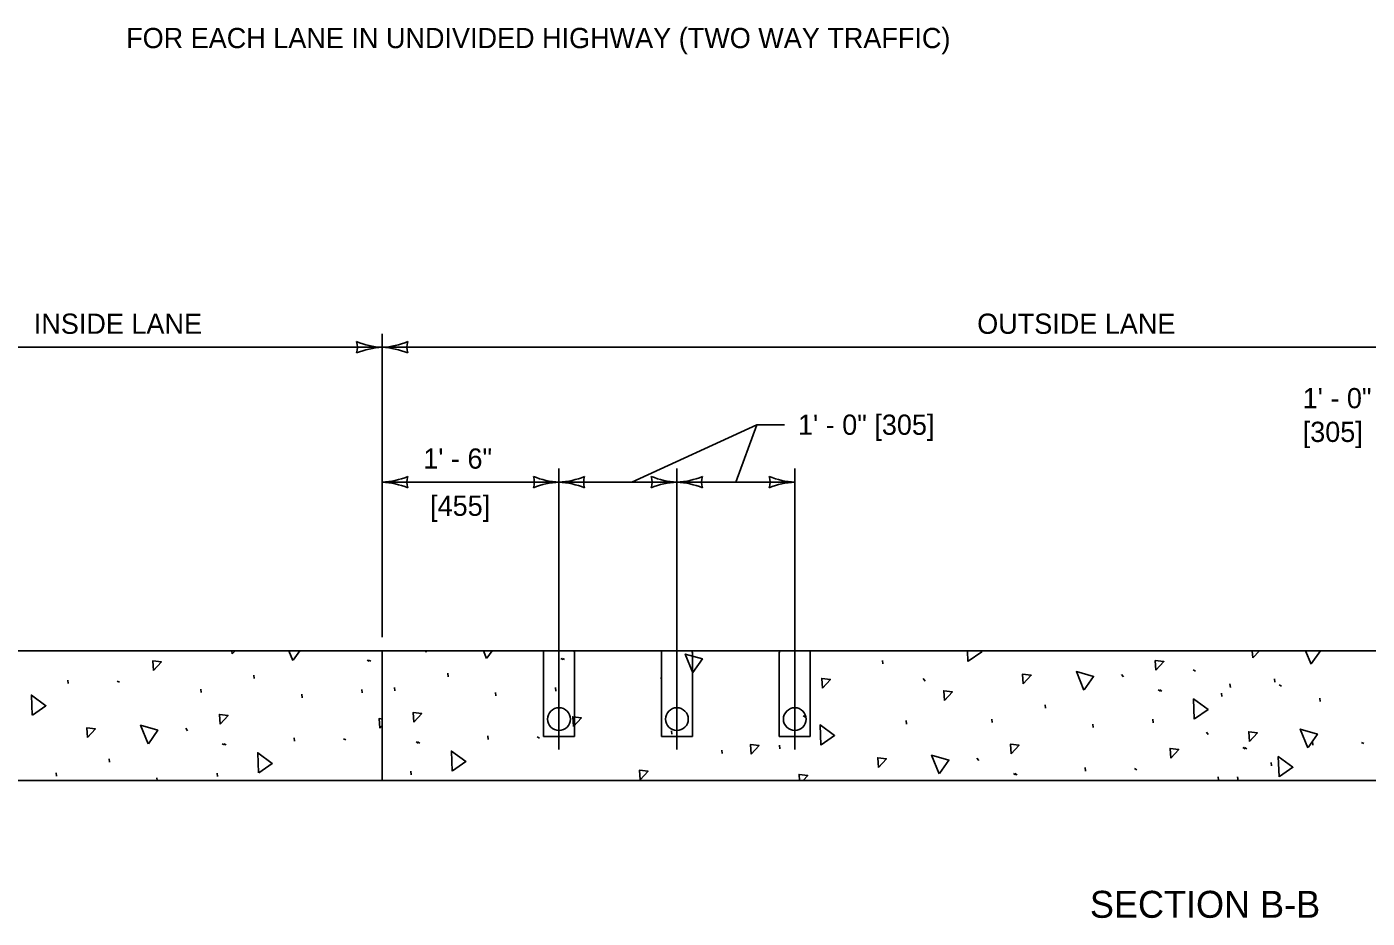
# Model space of a CAD drawing. Extents: x 49991.4 to 50021, y 49987.6 to 50011.4.
# Drawn here: x 50002.055 to 50006.035, y 49990.736 to 49993.381 of the extents above; entities that cross this region are included whole.
import ezdxf

# ---------------------------------------------------------------- set-up
doc = ezdxf.new("R2010")
doc.units = 0
for name, color, linetype in [('Level 1', 7, 'Continuous'), ('Level 2', 7, 'Continuous'), ('Level 3', 7, 'Continuous'), ('Level 4', 7, 'Continuous'), ('Level 5', 7, 'Continuous'), ('Level 9', 7, 'Continuous')]:
    doc.layers.add(name, color=color, linetype=linetype)

msp = doc.modelspace()

# ---------------------------------------------------------------- linework, layer by layer
at = {"layer": 'Level 1'}
for p, q in [((50001.6187, 49991.5298), (50007.3102, 49991.5298)), ((50003.1103, 49991.5298), (50003.1103, 49991.1448)), ((50001.6187, 49991.1448), (50003.1125, 49991.1448)), ((50003.1125, 49991.1448), (50007.3102, 49991.1448))]:
    msp.add_line(p, q, dxfattribs=at)
at = {"layer": 'Level 3'}
for p, q in [((50003.1103, 49991.5698), (50003.1103, 49992.4698)), ((50003.1103, 49992.4298), (50001.6187, 49992.4298)), ((50007.3102, 49992.4298), (50003.1103, 49992.4298)), ((50004.2228, 49992.2002), (50004.3048, 49992.2002)), ((50003.6353, 49992.0298), (50003.1103, 49992.0298)), ((50003.9853, 49992.0298), (50003.6353, 49992.0298)), ((50004.3353, 49992.0298), (50003.9853, 49992.0298))]:
    msp.add_line(p, q, dxfattribs=at)
msp.add_lwpolyline([(50003.8515, 49992.0298), (50004.2228, 49992.2002), (50004.1603, 49992.0298)], dxfattribs=at)
for centre in [(50003.6353, 49991.3267), (50003.9853, 49991.3267), (50004.3353, 49991.3267)]:
    msp.add_circle(centre, 0.0338, dxfattribs=at)
for centre, radius, start, end in [((50003.1194, 49992.6519), 0.2223, 247.456, 267.6395), ((50002.9821, 49992.4298), 0.0548, 342.1388, 17.8612), ((50003.1218, 49992.1971), 0.233, 92.8273, 112.0772), ((50003.1011, 49992.6519), 0.2223, 272.3605, 292.544), ((50003.0988, 49992.1971), 0.233, 67.9228, 87.1727), ((50003.2385, 49992.4298), 0.0548, 162.1388, 197.8612), ((50003.1011, 49992.2519), 0.2223, 272.3605, 292.544), ((50003.0988, 49991.7971), 0.233, 67.9228, 87.1727), ((50003.2385, 49992.0298), 0.0548, 162.1388, 197.8612), ((50003.5071, 49992.0298), 0.0548, 342.1388, 17.8612), ((50003.6468, 49992.2625), 0.233, 247.9228, 267.1727), ((50003.6444, 49991.8076), 0.2223, 92.3605, 112.544), ((50003.6261, 49992.2519), 0.2223, 272.3605, 292.544), ((50003.6238, 49991.7971), 0.233, 67.9228, 87.1727), ((50003.7635, 49992.0298), 0.0548, 162.1388, 197.8612), ((50003.8571, 49992.0298), 0.0548, 342.1388, 17.8612), ((50003.9968, 49992.2625), 0.233, 247.9228, 267.1727), ((50003.9944, 49991.8076), 0.2223, 92.3605, 112.544), ((50003.9761, 49992.2519), 0.2223, 272.3605, 292.544), ((50003.9738, 49991.7971), 0.233, 67.9228, 87.1727), ((50004.1135, 49992.0298), 0.0548, 162.1388, 197.8612), ((50004.2071, 49992.0298), 0.0548, 342.1388, 17.8612), ((50004.3468, 49992.2625), 0.233, 247.9228, 267.1727), ((50004.3444, 49991.8076), 0.2223, 92.3605, 112.544)]:
    msp.add_arc(centre, radius, start, end, dxfattribs=at)
at = {"layer": 'Level 4'}
for p, q in [((50003.0654, 49991.5018), (50003.0721, 49991.4985)), ((50003.0702, 49991.5018), (50003.0769, 49991.4985)), ((50003.6406, 49991.5071), (50003.6473, 49991.5038)), ((50003.6453, 49991.5071), (50003.652, 49991.5038)), ((50004.5965, 49991.4904), (50004.5955, 49991.5006)), ((50005.9849, 49991.5298), (50005.9854, 49991.5291)), ((50002.7308, 49991.4474), (50002.7297, 49991.4575)), ((50003.3059, 49991.4527), (50003.3049, 49991.4628)), ((50005.3056, 49991.4595), (50005.3111, 49991.4519)), ((50005.518, 49991.4727), (50005.5247, 49991.4694)), ((50002.1784, 49991.4323), (50002.1773, 49991.4425)), ((50002.3237, 49991.4396), (50002.3304, 49991.4363)), ((50002.5732, 49991.4054), (50002.5721, 49991.4156)), ((50003.0509, 49991.4047), (50003.0498, 49991.4149)), ((50003.1483, 49991.4107), (50003.1472, 49991.4208)), ((50003.626, 49991.41), (50003.625, 49991.4202)), ((50003.94, 49991.4405), (50003.9389, 49991.4506)), ((50004.7169, 49991.4469), (50004.7224, 49991.4393)), ((50005.4139, 49991.4133), (50005.4206, 49991.41)), ((50005.4186, 49991.4133), (50005.4253, 49991.41)), ((50005.6284, 49991.4209), (50005.6273, 49991.4311)), ((50005.7608, 49991.436), (50005.7597, 49991.4461)), ((50005.7737, 49991.4283), (50005.7804, 49991.4249)), ((50002.8725, 49991.3904), (50002.8715, 49991.4006)), ((50003.4477, 49991.3957), (50003.4466, 49991.4059)), ((50005.6032, 49991.394), (50005.6021, 49991.4042)), ((50005.8953, 49991.3791), (50005.8942, 49991.3892)), ((50004.3603, 49991.3361), (50004.367, 49991.3328)), ((50005.0792, 49991.3588), (50005.0782, 49991.369)), ((50002.5273, 49991.2999), (50002.5329, 49991.2923)), ((50004.6666, 49991.3122), (50004.6655, 49991.3223)), ((50004.9216, 49991.3169), (50004.9205, 49991.327)), ((50005.221, 49991.3019), (50005.2199, 49991.312)), ((50005.3993, 49991.3162), (50005.3983, 49991.3263)), ((50002.8502, 49991.2613), (50002.8491, 49991.2715)), ((50002.9955, 49991.2687), (50003.0022, 49991.2654)), ((50003.2108, 49991.259), (50003.2175, 49991.2556)), ((50003.2156, 49991.259), (50003.2223, 49991.2557)), ((50003.4253, 49991.2666), (50003.4242, 49991.2768)), ((50003.5706, 49991.2739), (50003.5773, 49991.2706)), ((50003.9705, 49991.2817), (50003.9694, 49991.2918)), ((50005.5573, 49991.2885), (50005.5629, 49991.2809)), ((50005.8729, 49991.2499), (50005.8718, 49991.2601)), ((50006.0182, 49991.2573), (50006.0249, 49991.254)), ((50002.6357, 49991.2537), (50002.6423, 49991.2504)), ((50002.6404, 49991.2537), (50002.6471, 49991.2504)), ((50004.1194, 49991.2247), (50004.1184, 49991.2349)), ((50004.2906, 49991.239), (50004.2895, 49991.2492)), ((50005.6656, 49991.2423), (50005.6723, 49991.239)), ((50005.6704, 49991.2423), (50005.6771, 49991.239)), ((50002.301, 49991.1992), (50002.2999, 49991.2094)), ((50004.8758, 49991.2113), (50004.8813, 49991.2038)), ((50005.1986, 49991.1728), (50005.1975, 49991.1829)), ((50005.3439, 49991.1801), (50005.3506, 49991.1768)), ((50005.751, 49991.1879), (50005.7499, 49991.198)), ((50002.1434, 49991.1573), (50002.1423, 49991.1674)), ((50002.4425, 49991.1448), (50002.4417, 49991.1525)), ((50002.6211, 49991.1566), (50002.62, 49991.1668)), ((50003.1963, 49991.1619), (50003.1952, 49991.172)), ((50004.9841, 49991.1651), (50004.9908, 49991.1618)), ((50004.9889, 49991.1652), (50004.9956, 49991.1618)), ((50005.5934, 49991.1459), (50005.5923, 49991.156)), ((50005.6511, 49991.1452), (50005.65, 49991.1554))]:
    msp.add_line(p, q, dxfattribs=at)
for points in [[(50002.4314, 49991.4707), (50002.4292, 49991.4994), (50002.4549, 49991.4963), (50002.4314, 49991.4707)], [(50002.6651, 49991.5201), (50002.6644, 49991.5298)], [(50002.674, 49991.5298), (50002.6651, 49991.5201)], [(50002.8453, 49991.5011), (50002.8337, 49991.5298)], [(50002.8656, 49991.5298), (50002.846, 49991.5019)], [(50003.2402, 49991.5254), (50003.2399, 49991.5298)], [(50003.2443, 49991.5298), (50003.2402, 49991.5254)], [(50003.4204, 49991.5064), (50003.411, 49991.5298)], [(50003.437, 49991.5298), (50003.4211, 49991.5072)], [(50004.0325, 49991.4645), (50004.01, 49991.5198), (50004.0613, 49991.5052), (50004.0331, 49991.4652)], [(50004.8495, 49991.4978), (50004.8483, 49991.5298)], [(50004.8856, 49991.5298), (50004.8905, 49991.5262), (50004.8504, 49991.4983)], [(50005.4076, 49991.4718), (50005.4054, 49991.5005), (50005.4311, 49991.4974), (50005.4076, 49991.4718)], [(50005.6951, 49991.5087), (50005.6935, 49991.5298)], [(50005.7145, 49991.5298), (50005.6951, 49991.5087)], [(50005.868, 49991.4897), (50005.8518, 49991.5298)], [(50005.8963, 49991.5298), (50005.8687, 49991.4905)], [(50005.0135, 49991.4316), (50005.0114, 49991.4602), (50005.0371, 49991.4571), (50005.0135, 49991.4316)], [(50005.1937, 49991.4126), (50005.1713, 49991.468), (50005.2225, 49991.4533), (50005.1944, 49991.4134)], [(50004.4177, 49991.419), (50004.4155, 49991.4477), (50004.4412, 49991.4446), (50004.4177, 49991.419)], [(50002.0713, 49991.3382), (50002.0691, 49991.3979), (50002.1123, 49991.3666), (50002.0722, 49991.3387)], [(50004.7798, 49991.3822), (50004.7776, 49991.4108), (50004.8034, 49991.4077), (50004.7798, 49991.3822)], [(50005.5213, 49991.3268), (50005.5191, 49991.3865), (50005.5622, 49991.3552), (50005.5221, 49991.3273)], [(50002.6294, 49991.3123), (50002.6272, 49991.3409), (50002.6529, 49991.3378), (50002.6294, 49991.3123)], [(50003.2045, 49991.3175), (50003.2023, 49991.3462), (50003.228, 49991.3431), (50003.2045, 49991.3175)], [(50003.6783, 49991.305), (50003.6761, 49991.3337), (50003.7018, 49991.3306), (50003.6783, 49991.305)], [(50002.2353, 49991.272), (50002.2331, 49991.3006), (50002.2588, 49991.2975), (50002.2353, 49991.272)], [(50002.4155, 49991.253), (50002.393, 49991.3084), (50002.4443, 49991.2937), (50002.4162, 49991.2538)], [(50003.1031, 49991.2997), (50003.101, 49991.3284), (50003.1116, 49991.3271)], [(50003.1117, 49991.3091), (50003.1031, 49991.2997)], [(50004.4125, 49991.2496), (50004.4103, 49991.3094), (50004.4535, 49991.2781), (50004.4134, 49991.2501)], [(50005.8583, 49991.2416), (50005.8358, 49991.297), (50005.887, 49991.2823), (50005.8589, 49991.2424)], [(50005.6853, 49991.2606), (50005.6831, 49991.2892), (50005.7088, 49991.2861), (50005.6853, 49991.2606)], [(50002.743, 49991.1672), (50002.7408, 49991.2269), (50002.784, 49991.1956), (50002.7439, 49991.1677)], [(50003.3182, 49991.1725), (50003.316, 49991.2322), (50003.3592, 49991.2009), (50003.3191, 49991.173)], [(50004.2056, 49991.2225), (50004.2034, 49991.2512), (50004.2291, 49991.2481), (50004.2056, 49991.2225)], [(50004.764, 49991.1644), (50004.7415, 49991.2198), (50004.7928, 49991.2052), (50004.7646, 49991.1652)], [(50004.9778, 49991.2237), (50004.9756, 49991.2524), (50005.0013, 49991.2493), (50004.9778, 49991.2237)], [(50005.4516, 49991.2112), (50005.4494, 49991.2398), (50005.4751, 49991.2367), (50005.4516, 49991.2112)], [(50005.773, 49991.1558), (50005.7708, 49991.2155), (50005.814, 49991.1842), (50005.7739, 49991.1563)], [(50003.8763, 49991.1466), (50003.8741, 49991.1752), (50003.8998, 49991.1721), (50003.8763, 49991.1466)], [(50004.5838, 49991.1834), (50004.5816, 49991.2121), (50004.6073, 49991.209), (50004.5838, 49991.1834)], [(50004.3492, 49991.1448), (50004.3479, 49991.1627), (50004.3736, 49991.1596), (50004.3599, 49991.1448)]]:
    msp.add_lwpolyline(points, dxfattribs=at)
at = {"layer": 'Level 5'}
for p, q in [((50003.6353, 49992.0698), (50003.6353, 49991.2367)), ((50003.9853, 49992.0698), (50003.9853, 49991.2367)), ((50004.3353, 49992.0698), (50004.3353, 49991.2367))]:
    msp.add_line(p, q, dxfattribs=at)
at = {"layer": 'Level 9'}
for p, q in [((50003.5892, 49991.5239), (50003.5892, 49991.3561)), ((50003.6755, 49991.5298), (50003.595, 49991.5298)), ((50003.6814, 49991.3561), (50003.6814, 49991.5239)), ((50003.9392, 49991.5239), (50003.9392, 49991.3561)), ((50004.0255, 49991.5298), (50003.945, 49991.5298)), ((50004.0314, 49991.3561), (50004.0314, 49991.5239)), ((50004.2892, 49991.5239), (50004.2892, 49991.3561)), ((50004.3756, 49991.5298), (50004.295, 49991.5298)), ((50004.3814, 49991.3561), (50004.3814, 49991.5239)), ((50003.5892, 49991.3561), (50003.5892, 49991.2757)), ((50003.6814, 49991.2757), (50003.6814, 49991.3561)), ((50003.9392, 49991.3561), (50003.9392, 49991.2757)), ((50004.0314, 49991.2757), (50004.0314, 49991.3561)), ((50004.2892, 49991.3561), (50004.2892, 49991.2757)), ((50004.3814, 49991.2757), (50004.3814, 49991.3561)), ((50003.5892, 49991.2757), (50003.6814, 49991.2757)), ((50003.9392, 49991.2757), (50004.0314, 49991.2757)), ((50004.2892, 49991.2757), (50004.3814, 49991.2757))]:
    msp.add_line(p, q, dxfattribs=at)
for centre, start, end in [((50003.595, 49991.5239), 90, 180), ((50003.6755, 49991.5239), 0, 90), ((50003.945, 49991.5239), 90, 180), ((50004.0255, 49991.5239), 0, 90), ((50004.295, 49991.5239), 90, 180), ((50004.3756, 49991.5239), 0, 90)]:
    msp.add_arc(centre, 0.00583, start, end, dxfattribs=at)

# ---------------------------------------------------------------- texts
at = {"layer": 'Level 2'}
for s, height, p in [('FOR EACH LANE IN UNDIVIDED HIGHWAY (TWO WAY TRAFFIC)', 0.06, (50002.3502, 49993.3173)), ('INSIDE LANE', 0.06, (50002.0761, 49992.4698)), ('OUTSIDE LANE', 0.06, (50004.8768, 49992.4698)), ('1\' - 0"', 0.06, (50005.8431, 49992.249)), ('1\' - 0" [305]', 0.06, (50004.3448, 49992.1702)), ('[305]', 0.06, (50005.8431, 49992.149)), ('1\' - 6"', 0.06, (50003.2323, 49992.0698)), ('[455]', 0.06, (50003.2526, 49991.9298)), ('SECTION B-B', 0.08, (50005.2114, 49990.7374))]:
    msp.add_text(s, height=height, dxfattribs=at).set_placement(p)

doc.saveas('drawing.dxf')
